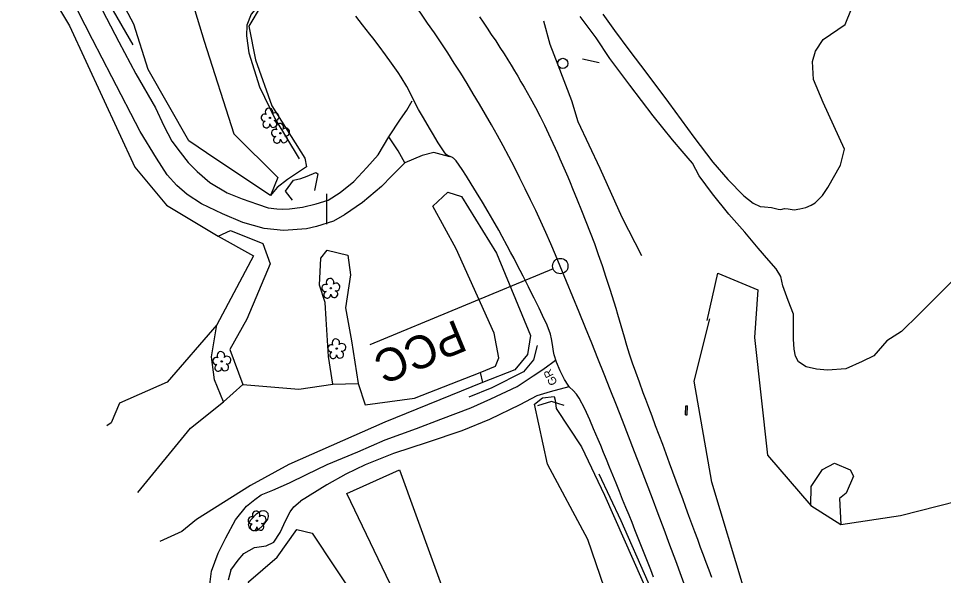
# Model space of a CAD drawing. Extents: x 478596 to 483012, y 490885 to 495165.
# Drawn here: x 480716.7 to 481167.1, y 492732.2 to 493003.6 of the extents above; entities that cross this region are included whole.
import ezdxf

# ---------------------------------------------------------------- set-up
doc = ezdxf.new("R2010")
doc.units = 0
for name, color, linetype in [('Exist Guardrail', 7, 'Continuous'), ('Exist Horizontal Alignment', 7, 'Continuous'), ('Exist Other Culture Area Outline', 7, 'Continuous'), ('Exist Other Culture Fence Line', 7, 'Continuous'), ('Exist Other Culture Gate', 7, 'Continuous'), ('Exist Other Culture Sign', 7, 'Continuous'), ('Exist Roads EOP', 7, 'Continuous'), ('Exist Roads EOP Other', 7, 'Continuous'), ('Exist Roads Soil', 7, 'Continuous'), ('Exist Roads Soil Text', 7, 'Continuous'), ('Exist Structure Minor Head and End Wall', 7, 'Continuous'), ('Exist Utilities Other Pole CELL', 7, 'Continuous'), ('Exist Vegetation Hedge Row', 7, 'Continuous'), ('Exist Vegetation Tree CELL', 7, 'Continuous'), ('Exist Vegetation Woods Line', 7, 'Continuous')]:
    doc.layers.add(name, color=color, linetype=linetype)

msp = doc.modelspace()

# ---------------------------------------------------------------- linework, layer by layer
at = {"layer": 'Exist Guardrail'}
for points in [[(480734.29, 493054.23), (480743.58, 493039.99), (480754.13, 493022.46), (480760.96, 493010.37), (480772.27, 492990.77)], [(481159.92, 492332.85), (481147.67, 492369.02), (481136.31, 492402.63), (481122.19, 492443.94), (481109.37, 492481.77), (481096.99, 492518.51), (481082.03, 492563.66), (481066.9, 492608.24), (481049.63, 492658.22), (481035.22, 492698.61), (481023.2, 492728.97), (481010.06, 492758.78), (480999.42, 492781.5)]]:
    msp.add_lwpolyline(points, dxfattribs=at)
at = {"layer": 'Exist Horizontal Alignment'}
msp.add_line((480977.02, 492881.53), (480887.74, 492844.53), dxfattribs=at)
msp.add_circle((480980.48, 492882.97), 3.75, dxfattribs=at)
for centre, radius, start, end in [((480394.24, 492639.96), 634.61, 22.51531, 56.41358), ((477373.51, 491387.79), 3904.58, 18.70399, 22.51531)]:
    msp.add_arc(centre, radius, start, end, dxfattribs=at)
at = {"layer": 'Exist Other Culture Area Outline'}
for points in [[(480850.15, 492915.02), (480846.62, 492919.52), (480850.64, 492924.74), (480854.1, 492925.62), (480857.17, 492926.83), (480861.51, 492928.53), (480862.37, 492927.91)], [(480862.37, 492927.91), (480860.83, 492919.84)]]:
    msp.add_lwpolyline(points, dxfattribs=at)
at = {"layer": 'Exist Other Culture Fence Line'}
for points in [[(480837.39, 493014.74), (480829.96, 493005.68), (480827.79, 493000.38), (480827.65, 492995.09), (480828.86, 492986.87), (480834.06, 492970.34), (480841.42, 492954.84), (480853.25, 492935.25)], [(481020.15, 492887.89), (481010.58, 492906.67), (480999.95, 492930.53), (480989.26, 492953.21), (480986.04, 492963.46), (480979.42, 492980.87), (480975.47, 492990.84), (480972.5, 493002.19)], [(480969.15, 492844.19), (480967.38, 492837.31), (480962.49, 492831.38), (480947.15, 492823.58), (480935.93, 492819.13)], [(480982.3, 492815.09), (480976.24, 492817), (480969.46, 492814.82)]]:
    msp.add_lwpolyline(points, dxfattribs=at)
at = {"layer": 'Exist Other Culture Gate'}
msp.add_line((480866.6, 492918.18), (480866.69, 492903.38), dxfattribs=at)
at = {"layer": 'Exist Other Culture Sign'}
msp.add_line((480999.46, 492982.02), (480991.33, 492983.77), dxfattribs=at)
at = {"layer": 'Exist Roads EOP'}
for points in [[(481025.82, 492731.43), (481024.49, 492734.94), (481023.2, 492738.28), (481021.93, 492741.53), (481020.66, 492744.76), (481019.39, 492747.99), (481018.11, 492751.21), (481016.8, 492754.51), (481015.41, 492757.97), (481013.94, 492761.6), (481012.4, 492765.39), (481010.82, 492769.28), (481009.23, 492773.21), (481007.63, 492777.16), (481006.02, 492781.15), (481004.45, 492785.05), (481002.95, 492788.74), (481001.52, 492792.21), (481000.17, 492795.48), (480998.91, 492798.5), (480996.7, 492803.74), (480994.87, 492807.99), (480992.37, 492813.34), (480989.64, 492818.66), (480988.33, 492820.54), (480986.7, 492822.4), (480985.01, 492824.02), (480984.27, 492824.9), (480982.51, 492827.7), (480980.44, 492831.88), (480978.68, 492836.14), (480977.52, 492839.73), (480977.15, 492841.38), (480976.7, 492844.71), (480976.23, 492847.44), (480975.65, 492849.79), (480974.01, 492854.17), (480971.82, 492858.95), (480970.12, 492862.44), (480967.73, 492867.31), (480966.37, 492870.07), (480965.02, 492872.78), (480962.38, 492878.06), (480961.01, 492880.73), (480959.55, 492883.57), (480957.97, 492886.57), (480956.3, 492889.73), (480954.69, 492892.75), (480952.19, 492897.4), (480950.52, 492900.5), (480947.7, 492905.44), (480945.37, 492909.38), (480942.6, 492914.02), (480939.72, 492918.77), (480937.1, 492923), (480934.75, 492926.74), (480932.68, 492929.97), (480929.71, 492934.19), (480928.81, 492935.2), (480928.46, 492935.53), (480928.19, 492935.75), (480927.96, 492935.9), (480927.72, 492936.03), (480925.6, 492936.87), (480924.96, 492937.32), (480924.18, 492938.18), (480921.03, 492943.07), (480918.31, 492947.62), (480916.77, 492950.21), (480913.86, 492955.16), (480911.5, 492959.29), (480909.82, 492962.36), (480908.22, 492965.69), (480905.68, 492970.4), (480902.97, 492974.95), (480901.5, 492977.2), (480898.33, 492981.73), (480895.33, 492985.9), (480892.21, 492990.08), (480889.15, 492994.08), (480887.78, 492995.87), (480884.22, 493000.53), (480880.91, 493004.73)], [(480941.15, 493004.38), (480942.96, 493001.71), (480944.88, 492998.86), (480946.9, 492995.84), (480949.02, 492992.63), (480951.12, 492989.42), (480953.09, 492986.37), (480954.9, 492983.48), (480956.57, 492980.76), (480958.17, 492978.11), (480959.75, 492975.44), (480961.32, 492972.77), (480962.89, 492970.08), (480965.81, 492964.91), (480968.36, 492960.2), (480970.65, 492955.81), (480972.76, 492951.59), (480974.81, 492947.35), (480976.9, 492942.87), (480979.13, 492937.93), (480980.33, 492935.21), (480981.6, 492932.32), (480982.87, 492929.36), (480984.11, 492926.45), (480985.3, 492923.59), (480986.45, 492920.77), (480988.68, 492915.28), (480990.85, 492909.99), (480992.97, 492904.74), (480995.09, 492899.36), (480997.12, 492893.96), (480999, 492888.65), (481000.83, 492883.24), (481002.68, 492877.56), (481003.62, 492874.62), (481004.57, 492871.63), (481005.53, 492868.58), (481006.51, 492865.47), (481007.45, 492862.4), (481008.35, 492859.46), (481009.98, 492853.95), (481011.56, 492848.49), (481012.79, 492844.39), (481014.07, 492840.25), (481015.53, 492835.84), (481017.11, 492831.36), (481018.81, 492826.63), (481020.72, 492821.39), (481021.94, 492818.09), (481023.37, 492814.28), (481025, 492809.94), (481026.73, 492805.34), (481028.45, 492800.77), (481030.17, 492796.21), (481031.87, 492791.68), (481033.56, 492787.18), (481035.2, 492782.73), (481036.82, 492778.33), (481038.39, 492773.99), (481039.93, 492769.73), (481041.45, 492765.57), (481042.93, 492761.51), (481044.38, 492757.56), (481045.81, 492753.69), (481047.23, 492749.86), (481048.63, 492746.08), (481050.02, 492742.35), (481051.4, 492738.65), (481052.75, 492734.99), (481054.08, 492731.34)]]:
    msp.add_lwpolyline(points, dxfattribs=at)
at = {"layer": 'Exist Roads EOP Other'}
msp.add_lwpolyline([(480926.66, 492936.1), (480922.51, 492937.29), (480918.92, 492938.36), (480913.14, 492936.84), (480904.76, 492933.28), (480901.46, 492939.15), (480896.91, 492945.89), (480902.67, 492954.59), (480905.68, 492958.98), (480908.39, 492963.45)], dxfattribs=at)
at = {"layer": 'Exist Roads Soil'}
for points in [[(480836.23, 492901.3), (480825.85, 492904.14), (480816.04, 492908.4), (480805.75, 492913.33), (480798.74, 492917.81), (480793.73, 492922.17), (480788.99, 492927.46), (480783.78, 492935.47), (480775.9, 492948.54), (480762.17, 492975.19), (480752.7, 492993.36), (480741.93, 493014.47), (480733.78, 493029.56), (480725.94, 493041.88), (480720.54, 493049.96)], [(480755.43, 493011.44), (480765.56, 492992.25), (480773.81, 492976.53), (480783.4, 492960.08), (480787.49, 492951.25), (480791.33, 492943.86), (480795.43, 492938.42), (480799.32, 492933.36), (480803.73, 492929.08), (480809.83, 492923.64), (480818.3, 492918.64), (480825.49, 492915.64), (480832.97, 492913.04), (480838.19, 492911.4), (480842.45, 492910.77), (480845.29, 492910.74), (480848.64, 492910.85), (480854.99, 492911.66), (480861.67, 492913.2), (480867.41, 492915.1), (480873.23, 492918.74), (480879.96, 492924.23), (480886.32, 492930.94), (480891.84, 492937.08), (480896.91, 492945.89)], [(481110.81, 492921.3), (481116.98, 492932.15), (481118.89, 492939.92), (481108.54, 492962.58), (481103.81, 492973.77), (481103.29, 492982.63), (481104.77, 492987.65), (481108.51, 492993.36), (481119.19, 493000.59), (481122.35, 493008.26)], [(481094.07, 492859.57), (481091.47, 492866.24), (481088.91, 492873.4), (481087.94, 492877.83), (481085.56, 492881.66), (481082.07, 492885.59), (481076.83, 492891.74), (481070.39, 492899.4), (481062.54, 492908.23), (481054.64, 492918.13), (481048.18, 492926.93), (481044.81, 492933.14), (481042.73, 492935.44), (481039.75, 492938.95), (481035.19, 492944.47), (481025.68, 492956.16), (481014.39, 492971.16), (481004.62, 492984.12), (480998, 492994.13), (480990.09, 493004.5)], [(481001.23, 493005.66), (481006.93, 492997.76), (481013.81, 492988.3), (481022.54, 492976.81), (481033.2, 492962.59), (481045.54, 492945.79), (481054.82, 492933.62), (481062.05, 492925.19), (481069.83, 492917.23), (481074.34, 492913.61), (481077.76, 492912.05), (481079.97, 492911.88), (481083.36, 492911.51), (481086.62, 492910.65), (481087.95, 492910.51), (481089.6, 492910.94), (481091.51, 492910.85), (481094.33, 492910.37), (481097.1, 492910.87), (481099.99, 492911.44), (481102.65, 492912.66), (481104.51, 492913.81), (481108.1, 492917.26), (481110.81, 492921.3)], [(480904.76, 492933.28), (480898.48, 492926.91), (480893.36, 492921.79), (480884.14, 492913.96), (480875.43, 492907.97), (480869.98, 492904.84), (480861.71, 492902.17), (480856.85, 492901.09), (480845.7, 492900.31), (480836.23, 492901.3)], [(481171.34, 492875.64), (481164.53, 492868.71), (481155.29, 492859.56), (481146.58, 492851.03), (481139.49, 492846.6), (481133.08, 492839.22), (481127.43, 492836.51), (481119.54, 492832.82), (481110.63, 492832.23), (481105.29, 492832.71), (481100.16, 492833.83), (481096.47, 492836.34), (481095, 492839.13), (481094.29, 492842.43), (481094.05, 492847.4), (481094.07, 492859.57)], [(480971.46, 492832.22), (480973.7, 492833.83), (480976.82, 492836.21), (480978.15, 492837.18)], [(480808.98, 492721.41), (480810.67, 492734.37), (480813.96, 492743.02), (480817.67, 492750.64), (480822.4, 492759.28), (480827.6, 492765.96), (480831.68, 492769.19), (480834.87, 492771.53), (480840.55, 492773.82), (480848.56, 492777.43), (480856.84, 492781.47), (480867, 492786.25), (480881.95, 492792.54), (480895.21, 492798.25), (480910.39, 492803.87), (480922.36, 492808.33), (480936.91, 492813.83), (480946.64, 492818.22), (480959.55, 492824.32), (480967.21, 492829.54), (480971.46, 492832.22)], [(480984.63, 492824.12), (480975.58, 492821.69)], [(480975.58, 492821.69), (480969.05, 492819.78), (480960.81, 492815.39), (480946.05, 492808.24), (480932.6, 492802.73), (480915.65, 492797.03), (480899.26, 492791.61), (480885.53, 492786.06), (480876.07, 492781.56), (480866.73, 492776.38), (480854.01, 492768.4)], [(480820.08, 492734.8), (480823.63, 492739.61), (480826.42, 492742.89), (480831.64, 492745.88), (480837.29, 492746.64), (480841.01, 492748.51), (480844.13, 492753.12), (480846.85, 492759.14), (480848.87, 492763.21), (480850.76, 492765.59), (480854.01, 492768.4)], [(480830.45, 492754.07), (480829.17, 492755.29), (480828.59, 492757.17), (480829.81, 492759.32), (480832.68, 492762.48), (480834.8, 492763.77), (480836.09, 492763.92), (480837.15, 492763.56), (480838.01, 492762.5), (480838.24, 492760.97), (480837.96, 492759.64), (480835.59, 492756.6), (480833.43, 492754.45), (480832.61, 492754.02), (480831.67, 492753.91), (480830.45, 492754.07)], [(480820.08, 492734.8), (480818.72, 492729.95)]]:
    msp.add_lwpolyline(points, dxfattribs=at)
at = {"layer": 'Exist Structure Minor Head and End Wall'}
for p, q in [((481041.39, 492810.46), (481041.61, 492814.91)), ((481041.61, 492814.91), (481042.44, 492814.87)), ((481042.22, 492810.42), (481042.44, 492814.87)), ((481041.39, 492810.46), (481042.22, 492810.42))]:
    msp.add_line(p, q, dxfattribs=at)
at = {"layer": 'Exist Utilities Other Pole CELL'}
msp.add_circle((480981.71, 492981.7), 2.46, dxfattribs=at)
at = {"layer": 'Exist Vegetation Hedge Row'}
for points in [[(480785.66, 493082.33), (480792.85, 493085.7), (480797.51, 493071.62), (480801.79, 493059.31), (480804.35, 493054.77), (480807.13, 493053.68), (480816.31, 493053.32), (480826.06, 493049.57), (480837.61, 493039.41), (480848.28, 493021.88), (480834.86, 493009.84), (480828.82, 492999.78), (480832.03, 492983.49), (480839.99, 492961.09), (480856.08, 492935.53), (480856.93, 492931.37), (480847.59, 492925.15), (480842.61, 492921.18), (480839.34, 492917.38)], [(480941.52, 492831.11), (480948.88, 492834.16), (480950.54, 492838.31), (480948.36, 492850.21), (480929.77, 492891.42), (480918.34, 492912.08), (480925.79, 492919.02), (480932.4, 492916.78), (480949.38, 492889.32), (480965.99, 492849.1), (480964.5, 492839.91), (480958.38, 492832.46), (480942.57, 492826.26)], [(480813.95, 492897.48), (480819.83, 492900.36), (480835.59, 492893.98), (480839.17, 492884.07), (480827.82, 492857.12), (480819.52, 492842.3), (480825.9, 492825.33)], [(480869.79, 492825.49), (480867.56, 492838.86), (480866.51, 492857.09), (480866.05, 492865.28), (480863.2, 492873.67), (480863.82, 492886.84), (480866.97, 492890.69), (480877, 492888.26), (480878.34, 492878.65), (480875.82, 492862.59), (480878.87, 492846.48), (480882.1, 492825.74)], [(480816.49, 492816.85), (480812.08, 492827.56), (480810.56, 492838.82), (480813.24, 492854.4)], [(481071.23, 492513.93), (481054.53, 492571.95), (481012.28, 492696.13), (480993.86, 492749.69), (480974.19, 492786.51), (480967.88, 492815.61), (480971.79, 492818.74), (480977.52, 492819.35), (480978.02, 492817.58), (480978.51, 492813.62), (480990.77, 492794.88), (481002, 492771.37), (481025.27, 492718.92), (481050.65, 492644.35), (481078.23, 492565.63), (481100.49, 492496.39)], [(481102.43, 492766.39), (481102.69, 492775.65), (481108.11, 492783.93), (481114.02, 492787.01), (481121.58, 492783.72), (481123.27, 492780.66), (481119.65, 492772.35), (481116.48, 492769.79), (481117.1, 492757.03)]]:
    msp.add_lwpolyline(points, dxfattribs=at)
at = {"layer": 'Exist Vegetation Tree CELL'}
for p, q in [((480839.06, 492955.11), (480839.06, 492955.11)), ((480844.22, 492947.66), (480844.22, 492947.66)), ((480868.74, 492872.17), (480868.74, 492872.17)), ((480871.59, 492842.72), (480871.59, 492842.72)), ((480815.6, 492836.54), (480815.6, 492836.54)), ((480832.78, 492758.88), (480832.78, 492758.88))]:
    msp.add_line(p, q, dxfattribs=at)
for centre in [(480839.06, 492955.11), (480844.22, 492947.66), (480868.74, 492872.17), (480871.59, 492842.72), (480815.6, 492836.54), (480832.78, 492758.88)]:
    msp.add_circle(centre, 0.326, dxfattribs=at)
for centre, radius, start, end in [((480838.68, 492957.99), 1.86, 330.1651, 219.7134), ((480836.46, 492955.27), 1.73, 62.6636, 279.3457), ((480837.36, 492951.99), 1.69, 111.5671, 6.231), ((480840.73, 492952.21), 1.7, 181.2822, 74.56), ((480841.61, 492955.7), 1.9, 257.1011, 134.1999), ((480841.62, 492947.82), 1.73, 62.6636, 279.3457), ((480843.84, 492950.54), 1.86, 330.1651, 219.7134), ((480846.77, 492948.25), 1.9, 257.1011, 134.1999), ((480842.52, 492944.54), 1.69, 111.5671, 6.231), ((480845.9, 492944.76), 1.7, 181.2822, 74.56), ((480868.35, 492875.04), 1.86, 330.1651, 219.7134), ((480866.13, 492872.32), 1.73, 62.6636, 279.3457), ((480871.28, 492872.76), 1.9, 257.1011, 134.1999), ((480867.03, 492869.05), 1.69, 111.5671, 6.231), ((480870.41, 492869.27), 1.7, 181.2822, 74.56), ((480871.2, 492845.59), 1.86, 330.1651, 219.7134), ((480815.22, 492839.42), 1.86, 330.1651, 219.7134), ((480868.98, 492842.87), 1.73, 62.6636, 279.3457), ((480869.88, 492839.6), 1.69, 111.5671, 6.231), ((480873.26, 492839.82), 1.7, 181.2822, 74.56), ((480874.14, 492843.31), 1.9, 257.1011, 134.1999), ((480813, 492836.7), 1.73, 62.6636, 279.3457), ((480818.15, 492837.13), 1.9, 257.1011, 134.1999), ((480813.9, 492833.42), 1.69, 111.5671, 6.231), ((480817.27, 492833.64), 1.7, 181.2822, 74.56), ((480830.18, 492759.03), 1.73, 62.6636, 279.3457), ((480832.4, 492761.75), 1.86, 330.1651, 219.7134), ((480835.33, 492759.47), 1.9, 257.1011, 134.1999), ((480831.08, 492755.76), 1.69, 111.5671, 6.231), ((480834.46, 492755.98), 1.7, 181.2822, 74.56)]:
    msp.add_arc(centre, radius, start, end, dxfattribs=at)
at = {"layer": 'Exist Vegetation Woods Line'}
for points in [[(480785.66, 493082.33), (480785.66, 493082.33), (480789.12, 493051.96), (480807.06, 492992.55), (480821.45, 492947.33), (480842.94, 492926.16), (480839.34, 492917.38), (480812.74, 492935.09), (480799.61, 492943.95), (480779.83, 492978.74), (480772.8, 493000.8), (480749.44, 493044.91), (480730.58, 493076.57)], [(480716.65, 493041.49), (480741.51, 492999.94), (480773.32, 492931.13), (480788.68, 492912.69), (480813.95, 492897.48), (480831.05, 492888.02), (480813.24, 492854.4), (480789.12, 492826.33), (480765.86, 492816.22), (480761.77, 492806.65), (480759.63, 492805.16)], [(481051.97, 492856.4), (481057.27, 492879.51), (481076.75, 492871.43), (481075.03, 492848.22)], [(481200.38, 492382.62), (481135.69, 492556.19), (481093.4, 492673.11), (481070.04, 492725.37), (481054.31, 492777.66), (481045.71, 492826.93), (481053.22, 492857.22)], [(481075.03, 492848.22), (481081.37, 492790.8), (481102.43, 492766.39), (481117.1, 492757.03), (481146.17, 492761.51), (481183.08, 492770.86), (481226.09, 492789.67), (481274.85, 492832.35), (481307.78, 492849.11), (481312.32, 492853.29)], [(480882.1, 492825.74), (480885.52, 492815.41), (480909.45, 492818.67), (480941.52, 492831.11)], [(480941.52, 492831.11), (480942.57, 492826.26)], [(480774.75, 492772.58), (480800.46, 492804.03), (480816.49, 492816.85), (480825.9, 492825.33), (480853.2, 492822.96), (480869.79, 492825.49), (480882.1, 492825.74)], [(480942.57, 492826.26), (480895.05, 492806.88), (480848.34, 492786.23), (480829.61, 492775.98), (480803.31, 492759.47), (480796.24, 492753.71), (480785.47, 492748.75)], [(480942.23, 492624.03), (480920.55, 492680.49), (480876.54, 492772.09), (480902.13, 492783.76), (480925.98, 492717.91), (480943.52, 492676.81), (480959.55, 492628.24), (480942.23, 492624.03)], [(480893.46, 492655.24), (480857.8, 492661.41), (480838.21, 492688.86), (480828.68, 492729.11), (480842.69, 492741.13), (480852.25, 492754.56), (480859.73, 492752.9), (480882, 492719.02), (480881.77, 492692.66), (480893.46, 492655.24)]]:
    msp.add_lwpolyline(points, dxfattribs=at)

# ---------------------------------------------------------------- texts
at = {"layer": 'Exist Horizontal Alignment'}
msp.add_text('PCC', height=16, rotation=202.5153, dxfattribs=at).set_placement((480930.02, 492857.18))
at = {"layer": 'Exist Roads Soil Text'}
msp.add_text('GR', height=4, rotation=116.5228, dxfattribs=at).set_placement((480979.22, 492826.02))

doc.saveas('drawing.dxf')
